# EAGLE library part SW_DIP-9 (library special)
DIP SWITCH
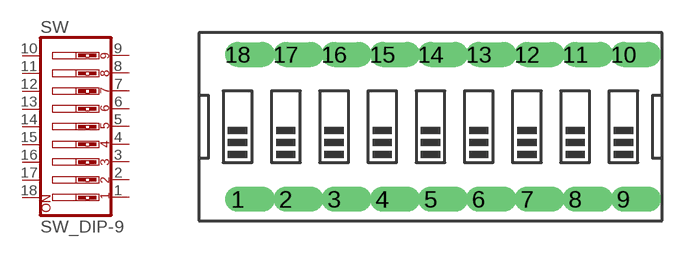
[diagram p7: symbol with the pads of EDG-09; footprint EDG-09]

Designator prefix SW

## SW_DIP-9  [EDG-09]
1  1  pas
2  2  pas
3  3  pas
4  4  pas
5  5  pas
6  6  pas
7  7  pas
8  8  pas
9  9  pas
10  10  pas
11  11  pas
12  12  pas
13  13  pas
14  14  pas
15  15  pas
16  16  pas
17  17  pas
18  18  pas

## Footprint EDG-09 (pad centres in mm)
DIP SWITCH
drill 0.813 offset: 1 -10.16,-3.81; 2 -7.62,-3.81; 3 -5.08,-3.81; 4 -2.54,-3.81; 5 0,-3.81; 6 2.54,-3.81; 7 5.08,-3.81; 8 7.62,-3.81; 9 10.16,-3.81; 10 10.16,3.81; 11 7.62,3.81; 12 5.08,3.81; 13 2.54,3.81; 14 0,3.81; 15 -2.54,3.81; 16 -5.08,3.81; 17 -7.62,3.81; 18 -10.16,3.81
